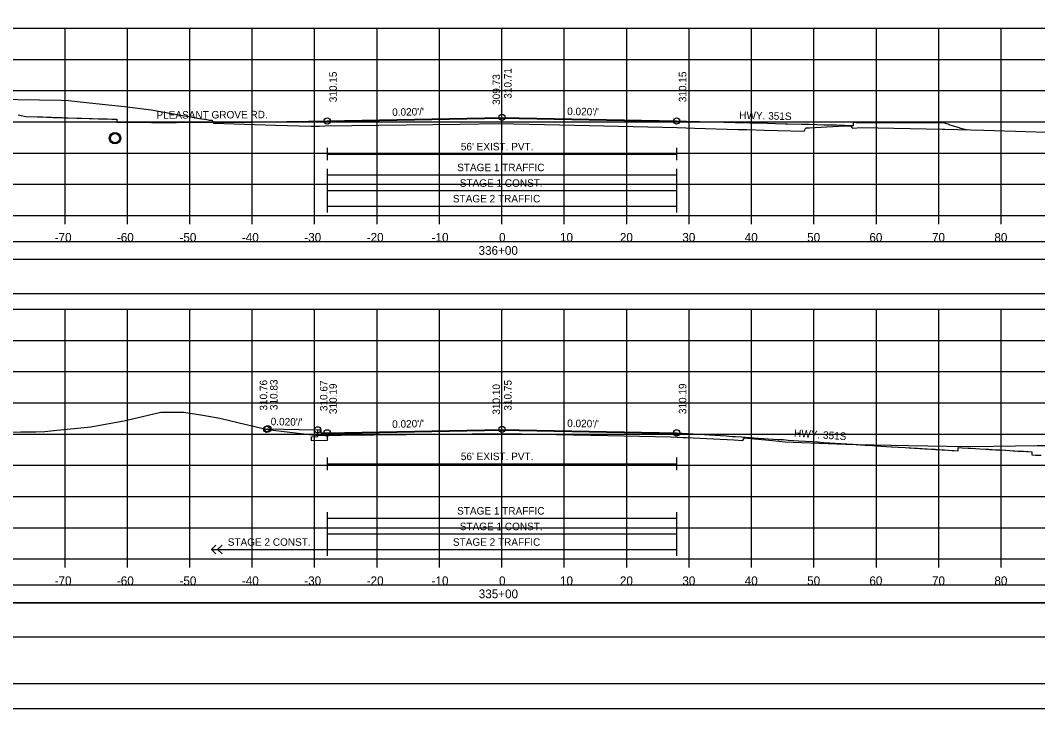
# Model space of a CAD drawing. Extents: x 1368122 to 1710785, y 373130 to 557566.
# Drawn here: x 1370611.8 to 1370774.8, y 373343.7 to 373453.9 of the extents above; entities that cross this region are included whole.
import ezdxf

# ---------------------------------------------------------------- set-up
doc = ezdxf.new("R2010")
doc.units = 0
for name, color, linetype in [('R_Alt Surface', 7, 'Continuous'), ('R_Axis', 7, 'Continuous'), ('R_Axis Annot', 7, 'Continuous'), ('R_Border', 7, 'Continuous'), ('R_Exist Surface', 7, 'Continuous'), ('R_Fin Surface', 7, 'Continuous'), ('R_Grid', 7, 'Continuous'), ('R_No Plot', 7, 'Continuous'), ('R_Striping', 7, 'Continuous'), ('R_Water', 7, 'Continuous'), ('R_Xsect Elev', 7, 'Continuous'), ('R_Xsect Slope', 7, 'Continuous')]:
    doc.layers.add(name, color=color, linetype=linetype)

msp = doc.modelspace()

# ---------------------------------------------------------------- linework, layer by layer
for points in [[(1370539.77, 373415.64), (1370838.07, 373415.64), (1370838.07, 373418.46), (1370539.77, 373418.46)], [(1370539.77, 373410.17), (1370838.07, 373410.17), (1370838.07, 373415.58), (1370539.77, 373415.58)], [(1370539.77, 373360.64), (1370838.07, 373360.64), (1370838.07, 373363.46), (1370539.77, 373363.46)], [(1370539.77, 373355.17), (1370838.07, 373355.17), (1370838.07, 373360.58), (1370539.77, 373360.58)]]:
    msp.add_lwpolyline(points, close=True)
at = {"layer": 'R_Alt Surface'}
for points in [[(1370716.92, 373437.63), (1370688.92, 373438.19), (1370660.92, 373437.63)], [(1370660.92, 373433.49), (1370660.92, 373431.49)], [(1370716.92, 373433.49), (1370716.92, 373431.49)], [(1370660.92, 373432.49), (1370716.92, 373432.49)], [(1370716.92, 373387.67), (1370688.92, 373388.23), (1370660.92, 373387.67), (1370660.92, 373386.59), (1370660.92, 373386.59), (1370658.42, 373386.54), (1370658.42, 373387.21), (1370659.42, 373387.23), (1370659.42, 373388.32)], [(1370660.92, 373383.87), (1370660.92, 373381.87)], [(1370716.92, 373383.87), (1370716.92, 373381.87)], [(1370660.92, 373382.87), (1370716.92, 373382.87)]]:
    msp.add_lwpolyline(points, dxfattribs=at)
at = {"layer": 'R_Axis'}
for p, q in [((1370538.92, 373422.65), (1370838.92, 373422.65)), ((1370618.92, 373421.25), (1370618.92, 373422.65)), ((1370628.92, 373421.25), (1370628.92, 373422.65)), ((1370638.92, 373421.25), (1370638.92, 373422.65)), ((1370648.92, 373421.25), (1370648.92, 373422.65)), ((1370658.92, 373421.25), (1370658.92, 373422.65)), ((1370668.92, 373421.25), (1370668.92, 373422.65)), ((1370678.92, 373421.25), (1370678.92, 373422.65)), ((1370688.92, 373421.25), (1370688.92, 373422.65)), ((1370698.92, 373421.25), (1370698.92, 373422.65)), ((1370708.92, 373421.25), (1370708.92, 373422.65)), ((1370718.92, 373421.25), (1370718.92, 373422.65)), ((1370728.92, 373421.25), (1370728.92, 373422.65)), ((1370738.92, 373421.25), (1370738.92, 373422.65)), ((1370748.92, 373421.25), (1370748.92, 373422.65)), ((1370758.92, 373421.25), (1370758.92, 373422.65)), ((1370768.92, 373421.25), (1370768.92, 373422.65)), ((1370538.92, 373367.65), (1370838.92, 373367.65)), ((1370618.92, 373366.25), (1370618.92, 373367.65)), ((1370628.92, 373366.25), (1370628.92, 373367.65)), ((1370638.92, 373366.25), (1370638.92, 373367.65)), ((1370648.92, 373366.25), (1370648.92, 373367.65)), ((1370658.92, 373366.25), (1370658.92, 373367.65)), ((1370668.92, 373366.25), (1370668.92, 373367.65)), ((1370678.92, 373366.25), (1370678.92, 373367.65)), ((1370688.92, 373366.25), (1370688.92, 373367.65)), ((1370698.92, 373366.25), (1370698.92, 373367.65)), ((1370708.92, 373366.25), (1370708.92, 373367.65)), ((1370718.92, 373366.25), (1370718.92, 373367.65)), ((1370728.92, 373366.25), (1370728.92, 373367.65)), ((1370738.92, 373366.25), (1370738.92, 373367.65)), ((1370748.92, 373366.25), (1370748.92, 373367.65)), ((1370758.92, 373366.25), (1370758.92, 373367.65)), ((1370768.92, 373366.25), (1370768.92, 373367.65))]:
    msp.add_line(p, q, dxfattribs=at)
at = {"layer": 'R_Border'}
msp.add_line((1370847.1, 373347.65), (1370530.92, 373347.65), dxfattribs=at)
at = {"layer": 'R_Exist Surface'}
for points in [[(1370607.91, 373441.27), (1370614.82, 373441.18), (1370618.26, 373441.14), (1370619.5, 373441.05), (1370621.83, 373440.79), (1370628.43, 373440.12), (1370632.71, 373439.57), (1370640.47, 373438.21), (1370641.65, 373438.01), (1370642.01, 373437.94), (1370642.07, 373437.94), (1370642.48, 373437.93), (1370642.51, 373437.86), (1370642.71, 373437.43), (1370652.65, 373437.11), (1370658.37, 373436.98), (1370659.71, 373436.98), (1370660.57, 373437), (1370682.25, 373437.3), (1370688.39, 373437.39), (1370698.2, 373437.18), (1370717.01, 373436.77), (1370718.39, 373436.71), (1370719.78, 373436.65), (1370726.76, 373436.43), (1370728.17, 373436.41), (1370730.98, 373436.32), (1370737.35, 373436.17), (1370737.46, 373436.39), (1370737.6, 373436.67), (1370737.86, 373436.67), (1370738.22, 373436.67), (1370742.87, 373436.95), (1370744.26, 373437.03), (1370744.72, 373437.03), (1370744.79, 373437.03), (1370745.02, 373436.69), (1370745.06, 373436.63), (1370746.61, 373436.75), (1370759.45, 373436.47), (1370759.89, 373436.46), (1370766.14, 373436.32), (1370771.21, 373436.18), (1370784.56, 373435.76)], [(1370610.45, 373387.94), (1370611.84, 373388), (1370614.26, 373388.02), (1370615.68, 373388.07), (1370617.15, 373388.19), (1370623.08, 373388.78), (1370628.63, 373389.82), (1370634.29, 373391.16), (1370636.64, 373391.15), (1370637.95, 373391.14), (1370641, 373390.65), (1370643.71, 373390.18), (1370646.61, 373389.49), (1370651.38, 373388.38), (1370658.52, 373387.53), (1370659.13, 373387.47), (1370660.37, 373387.44), (1370660.43, 373387.44), (1370663.18, 373387.47), (1370689.38, 373387.75), (1370705.89, 373387.4), (1370716.04, 373387.19), (1370717.98, 373387.12), (1370718.5, 373387.1), (1370726.1, 373386.71), (1370727.52, 373386.63), (1370727.67, 373386.87), (1370727.77, 373387.02), (1370728.09, 373387.02), (1370728.26, 373387.01), (1370732.27, 373386.59), (1370734.3, 373386.39), (1370735.57, 373386.36), (1370743.98, 373386.03), (1370745.76, 373385.98), (1370754.07, 373385.81), (1370760.24, 373385.68), (1370764.29, 373385.65), (1370774.67, 373385.83), (1370776.5, 373385.79)]]:
    msp.add_lwpolyline(points, dxfattribs=at)
at = {"layer": 'R_Fin Surface'}
for points in [[(1370611.41, 373438.77), (1370612.66, 373438.52), (1370614.44, 373438.46), (1370614.45, 373438.46), (1370614.45, 373438.46), (1370614.55, 373438.46), (1370614.57, 373438.46), (1370614.7, 373438.45), (1370615.11, 373438.44), (1370615.36, 373438.43), (1370615.93, 373438.41), (1370616.18, 373438.4), (1370616.56, 373438.39), (1370616.78, 373438.38), (1370617.04, 373438.37), (1370617.46, 373438.36), (1370617.95, 373438.34), (1370618.46, 373438.33), (1370618.73, 373438.32), (1370619.43, 373438.3), (1370620.79, 373438.25), (1370620.89, 373438.25), (1370620.98, 373438.25), (1370621.54, 373438.23), (1370622.78, 373438.2), (1370622.92, 373438.19), (1370623.29, 373438.18), (1370624.31, 373438.15), (1370625.68, 373438.11), (1370626.42, 373438.09), (1370626.77, 373438.09), (1370627.21, 373438.08), (1370627.21, 373437.77), (1370627.21, 373437.58), (1370628.15, 373437.58), (1370628.22, 373437.58), (1370628.35, 373437.58), (1370628.77, 373437.58), (1370629.01, 373437.58), (1370629.02, 373437.58), (1370630.26, 373437.58), (1370630.26, 373437.58), (1370630.59, 373437.58), (1370630.68, 373437.58), (1370632.79, 373437.57), (1370632.8, 373437.57), (1370632.88, 373437.57), (1370633.07, 373437.57), (1370633.21, 373437.57), (1370635.25, 373437.57), (1370635.59, 373437.56), (1370635.72, 373437.56), (1370636.52, 373437.56), (1370636.76, 373437.56), (1370644.68, 373437.6), (1370646.41, 373437.6), (1370646.42, 373437.6), (1370648.72, 373437.61), (1370652.18, 373437.66), (1370653.11, 373437.67), (1370654.05, 373437.68), (1370654.41, 373437.69), (1370654.49, 373437.69), (1370654.93, 373437.69), (1370660.92, 373437.8)], [(1370660.92, 373437.8), (1370688.92, 373438.36), (1370716.92, 373437.8)], [(1370716.92, 373437.8), (1370718.03, 373437.77), (1370718.24, 373437.76), (1370718.28, 373437.76), (1370718.48, 373437.76), (1370722.76, 373437.65), (1370722.94, 373437.65), (1370724.47, 373437.61), (1370726.27, 373437.56), (1370726.71, 373437.55), (1370726.84, 373437.55), (1370726.88, 373437.55), (1370728.65, 373437.5), (1370731.49, 373437.43), (1370732.77, 373437.4), (1370734.31, 373437.36), (1370734.72, 373437.35), (1370736.91, 373437.29), (1370738.04, 373437.26), (1370738.16, 373437.26), (1370740.51, 373437.2), (1370740.66, 373437.2), (1370741.94, 373437.16), (1370741.95, 373437.16), (1370742.42, 373437.15), (1370742.54, 373437.15), (1370743.76, 373437.11), (1370743.78, 373437.11), (1370743.8, 373437.11), (1370744.61, 373437.09), (1370745.23, 373437.08), (1370745.23, 373437.2), (1370745.23, 373437.58), (1370745.36, 373437.58), (1370745.71, 373437.57), (1370745.84, 373437.57), (1370745.94, 373437.57), (1370746.49, 373437.57), (1370746.6, 373437.57), (1370747, 373437.57), (1370748.29, 373437.57), (1370748.55, 373437.57), (1370748.92, 373437.57), (1370750.17, 373437.57), (1370750.22, 373437.57), (1370750.23, 373437.57), (1370750.35, 373437.57), (1370750.35, 373437.57), (1370750.36, 373437.57), (1370750.87, 373437.57), (1370750.9, 373437.57), (1370753.28, 373437.57), (1370753.75, 373437.56), (1370754.14, 373437.56), (1370754.26, 373437.56), (1370755.3, 373437.56), (1370756.08, 373437.55), (1370756.24, 373437.55), (1370756.87, 373437.55), (1370757.44, 373437.55), (1370759.05, 373437.53), (1370759.14, 373437.53), (1370759.7, 373437.53), (1370759.96, 373437.45), (1370759.97, 373437.45), (1370760.37, 373437.31), (1370760.7, 373437.2), (1370761.95, 373436.78), (1370762.42, 373436.63), (1370762.43, 373436.63), (1370762.59, 373436.59), (1370762.62, 373436.58), (1370762.77, 373436.54), (1370762.88, 373436.52), (1370762.9, 373436.51), (1370763.56, 373436.37)], [(1370651.23, 373388.41), (1370651.42, 373388.48), (1370656.42, 373388.38), (1370659.42, 373388.32), (1370659.92, 373388.32), (1370659.92, 373387.82), (1370660.92, 373387.84), (1370688.92, 373388.4), (1370716.92, 373387.84)], [(1370716.92, 373387.84), (1370724.84, 373387.34), (1370725.3, 373387.31), (1370725.83, 373387.27), (1370726.35, 373387.24), (1370727.33, 373387.18), (1370727.96, 373387.14), (1370728.57, 373387.1), (1370729.27, 373387.05), (1370732.41, 373386.85), (1370733.14, 373386.8), (1370733.96, 373386.75), (1370733.98, 373386.75), (1370734.77, 373386.69), (1370735.65, 373386.63), (1370736.5, 373386.58), (1370738.63, 373386.44), (1370739.54, 373386.38), (1370740.41, 373386.32), (1370740.48, 373386.32), (1370741.32, 373386.26), (1370741.43, 373386.26), (1370742.34, 373386.2), (1370743.29, 373386.14), (1370745.15, 373386.01), (1370745.67, 373385.98), (1370745.67, 373385.98), (1370745.76, 373385.98), (1370745.77, 373385.97), (1370745.96, 373385.96), (1370746.04, 373385.96), (1370746.05, 373385.96), (1370746.35, 373385.94), (1370746.75, 373385.91), (1370747.13, 373385.89), (1370747.24, 373385.88), (1370747.83, 373385.84), (1370748.28, 373385.81), (1370748.93, 373385.77), (1370749.47, 373385.74), (1370749.67, 373385.73), (1370750.48, 373385.67), (1370750.5, 373385.67), (1370751.37, 373385.62), (1370751.38, 373385.62), (1370751.41, 373385.62), (1370751.45, 373385.61), (1370751.45, 373385.61), (1370752.41, 373385.55), (1370752.42, 373385.55), (1370753.56, 373385.5), (1370754.18, 373385.46), (1370754.27, 373385.45), (1370754.27, 373385.45), (1370754.46, 373385.44), (1370754.46, 373385.44), (1370754.46, 373385.44), (1370755.04, 373385.4), (1370755.04, 373385.4), (1370755.51, 373385.37), (1370755.52, 373385.37), (1370755.86, 373385.34), (1370755.92, 373385.34), (1370755.97, 373385.34), (1370756.27, 373385.32), (1370756.68, 373385.29), (1370756.75, 373385.29), (1370756.77, 373385.29), (1370756.91, 373385.28), (1370757.05, 373385.27), (1370757.72, 373385.23), (1370757.99, 373385.21), (1370758.14, 373385.2), (1370758.28, 373385.2), (1370758.37, 373385.19), (1370758.53, 373385.18), (1370758.72, 373385.17), (1370759.4, 373385.13), (1370759.82, 373385.11), (1370761.07, 373385.03), (1370761.25, 373385.02), (1370761.26, 373385.02), (1370761.34, 373385.01), (1370762.05, 373384.97), (1370762.05, 373385.21), (1370762.05, 373385.47), (1370762.67, 373385.44), (1370763.63, 373385.38), (1370764.08, 373385.36), (1370764.79, 373385.32), (1370765.48, 373385.28), (1370766.38, 373385.23), (1370766.88, 373385.2), (1370767.07, 373385.19), (1370767.46, 373385.17), (1370768.03, 373385.13), (1370768.28, 373385.12), (1370768.7, 373385.1), (1370769.59, 373385.05), (1370769.62, 373385.05), (1370769.68, 373385.04), (1370770.31, 373385.01), (1370770.78, 373384.98), (1370770.94, 373384.97), (1370771.09, 373384.96), (1370771.61, 373384.93), (1370771.99, 373384.91), (1370772.34, 373384.89), (1370772.49, 373384.89), (1370772.99, 373384.86), (1370773.1, 373384.85), (1370773.12, 373384.85), (1370773.22, 373384.85), (1370773.82, 373384.81), (1370773.82, 373384.75), (1370773.83, 373384.31), (1370773.91, 373384.31), (1370774.42, 373384.28), (1370774.46, 373384.28), (1370774.54, 373384.28), (1370775.33, 373384.24)]]:
    msp.add_lwpolyline(points, dxfattribs=at)
at = {"layer": 'R_Grid'}
for p, q in [((1370538.92, 373452.65), (1370838.92, 373452.65)), ((1370618.92, 373422.65), (1370618.92, 373452.65)), ((1370628.92, 373422.65), (1370628.92, 373452.65)), ((1370638.92, 373422.65), (1370638.92, 373452.65)), ((1370648.92, 373422.65), (1370648.92, 373452.65)), ((1370658.92, 373422.65), (1370658.92, 373452.65)), ((1370668.92, 373422.65), (1370668.92, 373452.65)), ((1370678.92, 373422.65), (1370678.92, 373452.65)), ((1370688.92, 373422.65), (1370688.92, 373452.65)), ((1370698.92, 373422.65), (1370698.92, 373452.65)), ((1370708.92, 373422.65), (1370708.92, 373452.65)), ((1370718.92, 373422.65), (1370718.92, 373452.65)), ((1370728.92, 373422.65), (1370728.92, 373452.65)), ((1370738.92, 373422.65), (1370738.92, 373452.65)), ((1370748.92, 373422.65), (1370748.92, 373452.65)), ((1370758.92, 373422.65), (1370758.92, 373452.65)), ((1370768.92, 373422.65), (1370768.92, 373452.65)), ((1370538.92, 373447.65), (1370838.92, 373447.65)), ((1370538.92, 373442.65), (1370838.92, 373442.65)), ((1370538.92, 373437.65), (1370838.92, 373437.65)), ((1370538.92, 373432.65), (1370838.92, 373432.65)), ((1370538.92, 373427.65), (1370838.92, 373427.65)), ((1370538.92, 373422.65), (1370838.92, 373422.65)), ((1370538.92, 373407.65), (1370838.92, 373407.65)), ((1370618.92, 373367.65), (1370618.92, 373407.65)), ((1370628.92, 373367.65), (1370628.92, 373407.65)), ((1370638.92, 373367.65), (1370638.92, 373407.65)), ((1370648.92, 373367.65), (1370648.92, 373407.65)), ((1370658.92, 373367.65), (1370658.92, 373407.65)), ((1370668.92, 373367.65), (1370668.92, 373407.65)), ((1370678.92, 373367.65), (1370678.92, 373407.65)), ((1370688.92, 373367.65), (1370688.92, 373407.65)), ((1370698.92, 373367.65), (1370698.92, 373407.65)), ((1370708.92, 373367.65), (1370708.92, 373407.65)), ((1370718.92, 373367.65), (1370718.92, 373407.65)), ((1370728.92, 373367.65), (1370728.92, 373407.65)), ((1370738.92, 373367.65), (1370738.92, 373407.65)), ((1370748.92, 373367.65), (1370748.92, 373407.65)), ((1370758.92, 373367.65), (1370758.92, 373407.65)), ((1370768.92, 373367.65), (1370768.92, 373407.65)), ((1370538.92, 373402.65), (1370838.92, 373402.65)), ((1370538.92, 373397.65), (1370838.92, 373397.65)), ((1370538.92, 373392.65), (1370838.92, 373392.65)), ((1370538.92, 373387.65), (1370838.92, 373387.65)), ((1370538.92, 373382.65), (1370838.92, 373382.65)), ((1370538.92, 373377.65), (1370838.92, 373377.65)), ((1370538.92, 373372.65), (1370838.92, 373372.65)), ((1370538.92, 373367.65), (1370838.92, 373367.65))]:
    msp.add_line(p, q, dxfattribs=at)
at = {"layer": 'R_No Plot'}
msp.add_line((1370518.52, 373343.67), (1370851.85, 373343.67), dxfattribs=at)
for points in [[(1370518.51, 373557), (1370851.85, 373557), (1370851.85, 373343.66), (1370518.51, 373343.66)], [(1370764.84, 373553.11), (1370784.46, 373553.11), (1370784.46, 373543.23), (1370800.57, 373543.23), (1370823.77, 373543.23), (1370823.89, 373515.07), (1370847.1, 373515.07), (1370847.1, 373347.65), (1370530.92, 373347.65), (1370530.92, 373553.11)]]:
    msp.add_lwpolyline(points, close=True, dxfattribs=at)
for centre, radius in [((1370688.92, 373438.36), 0.5), ((1370660.92, 373437.8), 0.5), ((1370716.92, 373437.8), 0.5), ((1370626.93, 373435.03), 0.917), ((1370651.23, 373388.41), 0.5), ((1370651.42, 373388.48), 0.5), ((1370659.42, 373388.32), 0.5), ((1370660.92, 373387.84), 0.5), ((1370688.92, 373388.4), 0.5), ((1370716.92, 373387.84), 0.5)]:
    msp.add_circle(centre, radius, dxfattribs=at)
at = {"layer": 'R_Striping'}
for p, q in [((1370642.37, 373369.15), (1370643.08, 373369.85)), ((1370642.37, 373369.15), (1370660.92, 373369.15)), ((1370643.08, 373368.44), (1370642.37, 373369.15)), ((1370643.37, 373369.15), (1370644.08, 373369.85)), ((1370644.08, 373368.44), (1370643.37, 373369.15))]:
    msp.add_line(p, q, dxfattribs=at)
for points in [[(1370660.92, 373430.15), (1370660.92, 373423.15)], [(1370660.92, 373429.15), (1370716.92, 373429.15)], [(1370716.92, 373430.15), (1370716.92, 373423.15)], [(1370660.92, 373426.65), (1370716.92, 373426.65)], [(1370660.92, 373424.15), (1370716.92, 373424.15)], [(1370660.92, 373375.15), (1370660.92, 373368.15)], [(1370716.92, 373375.15), (1370716.92, 373368.15)], [(1370660.92, 373374.15), (1370716.92, 373374.15)], [(1370660.92, 373371.65), (1370716.92, 373371.65)], [(1370660.92, 373369.15), (1370716.92, 373369.15)]]:
    msp.add_lwpolyline(points, dxfattribs=at)
at = {"layer": 'R_Water'}
msp.add_circle((1370626.93, 373435.03), 0.75, dxfattribs=at)
at = {"layer": 'R_Xsect Elev'}
for p, q in [((1370688.92, 373437.37), (1370688.92, 373447.37)), ((1370688.92, 373387.75), (1370688.92, 373397.75))]:
    msp.add_line(p, q, dxfattribs=at)

# ---------------------------------------------------------------- texts
at = {"layer": 'R_Axis Annot'}
for s, p in [('-70', (1370617.26, 373418.45)), ('-60', (1370627.23, 373418.45)), ('-50', (1370637.26, 373418.45)), ('-40', (1370647.26, 373418.45)), ('-30', (1370657.26, 373418.45)), ('-20', (1370667.26, 373418.45)), ('-10', (1370677.66, 373418.45)), ('0', (1370688.46, 373418.45)), ('10', (1370698.23, 373418.45)), ('20', (1370707.83, 373418.45)), ('30', (1370717.83, 373418.45)), ('40', (1370727.83, 373418.45)), ('50', (1370737.83, 373418.45)), ('60', (1370747.8, 373418.45)), ('70', (1370757.83, 373418.45)), ('80', (1370767.83, 373418.45)), ('336+00', (1370685.18, 373416.35)), ('-70', (1370617.26, 373363.45)), ('-60', (1370627.23, 373363.45)), ('-50', (1370637.26, 373363.45)), ('-40', (1370647.26, 373363.45)), ('-30', (1370657.26, 373363.45)), ('-20', (1370667.26, 373363.45)), ('-10', (1370677.66, 373363.45)), ('0', (1370688.46, 373363.45)), ('10', (1370698.23, 373363.45)), ('20', (1370707.83, 373363.45)), ('30', (1370717.83, 373363.45)), ('40', (1370727.83, 373363.45)), ('50', (1370737.83, 373363.45)), ('60', (1370747.8, 373363.45)), ('70', (1370757.83, 373363.45)), ('80', (1370767.83, 373363.45)), ('335+00', (1370685.21, 373361.35))]:
    msp.add_text(s, height=1.4, dxfattribs=at).set_placement(p)
at = {"layer": 'R_Fin Surface'}
for s, rotation, p in [('PLEASANT GROVE RD.', 0.2634, (1370633.57, 373438.15)), ('HWY. 351S', 358.5519, (1370726.94, 373438.14)), ('HWY. 351S', 356.2386, (1370735.71, 373387.22))]:
    msp.add_text(s, height=1.2, rotation=rotation, dxfattribs=at).set_placement(p)
at = {"layer": 'R_Striping'}
for s, p in [('STAGE 1 TRAFFIC', (1370681.75, 373429.75)), ('STAGE 1 CONST.', (1370682.17, 373427.25)), ('STAGE 2 TRAFFIC', (1370681.07, 373424.75)), ('STAGE 1 TRAFFIC', (1370681.75, 373374.75)), ('STAGE 1 CONST.', (1370682.17, 373372.25)), ('STAGE 2 CONST.', (1370644.99, 373369.75)), ('STAGE 2 TRAFFIC', (1370681.07, 373369.75))]:
    msp.add_text(s, height=1.2, dxfattribs=at).set_placement(p)
at = {"layer": 'R_Water'}
for p in [(1370682.34, 373433.09), (1370682.34, 373383.47)]:
    msp.add_text("56' EXIST. PVT.", height=1.2, dxfattribs=at).set_placement(p)
at = {"layer": 'R_Xsect Elev'}
for s, p in [('310.15', (1370662.47, 373440.8)), ('309.73', (1370688.62, 373440.37)), ('310.71', (1370690.47, 373441.36)), ('310.15', (1370718.47, 373440.8)), ('310.76', (1370651.32, 373391.41)), ('310.83', (1370652.97, 373391.48)), ('310.67', (1370660.97, 373391.32)), ('310.75', (1370690.47, 373391.4)), ('310.19', (1370662.47, 373390.84)), ('310.10', (1370688.62, 373390.75)), ('310.19', (1370718.47, 373390.84))]:
    msp.add_text(s, height=1.2, rotation=90, dxfattribs=at).set_placement(p)
at = {"layer": 'R_Xsect Slope'}
for rotation, p in [(1.1458, (1370671.35, 373438.6)), (358.8542, (1370699.37, 373438.75)), (358.8542, (1370651.87, 373389.07)), (1.1458, (1370671.35, 373388.64)), (358.8542, (1370699.37, 373388.79))]:
    msp.add_text("0.020'/'", height=1.2, rotation=rotation, dxfattribs=at).set_placement(p)

doc.saveas('drawing.dxf')
